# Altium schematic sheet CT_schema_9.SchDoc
size 405 x 220 mm
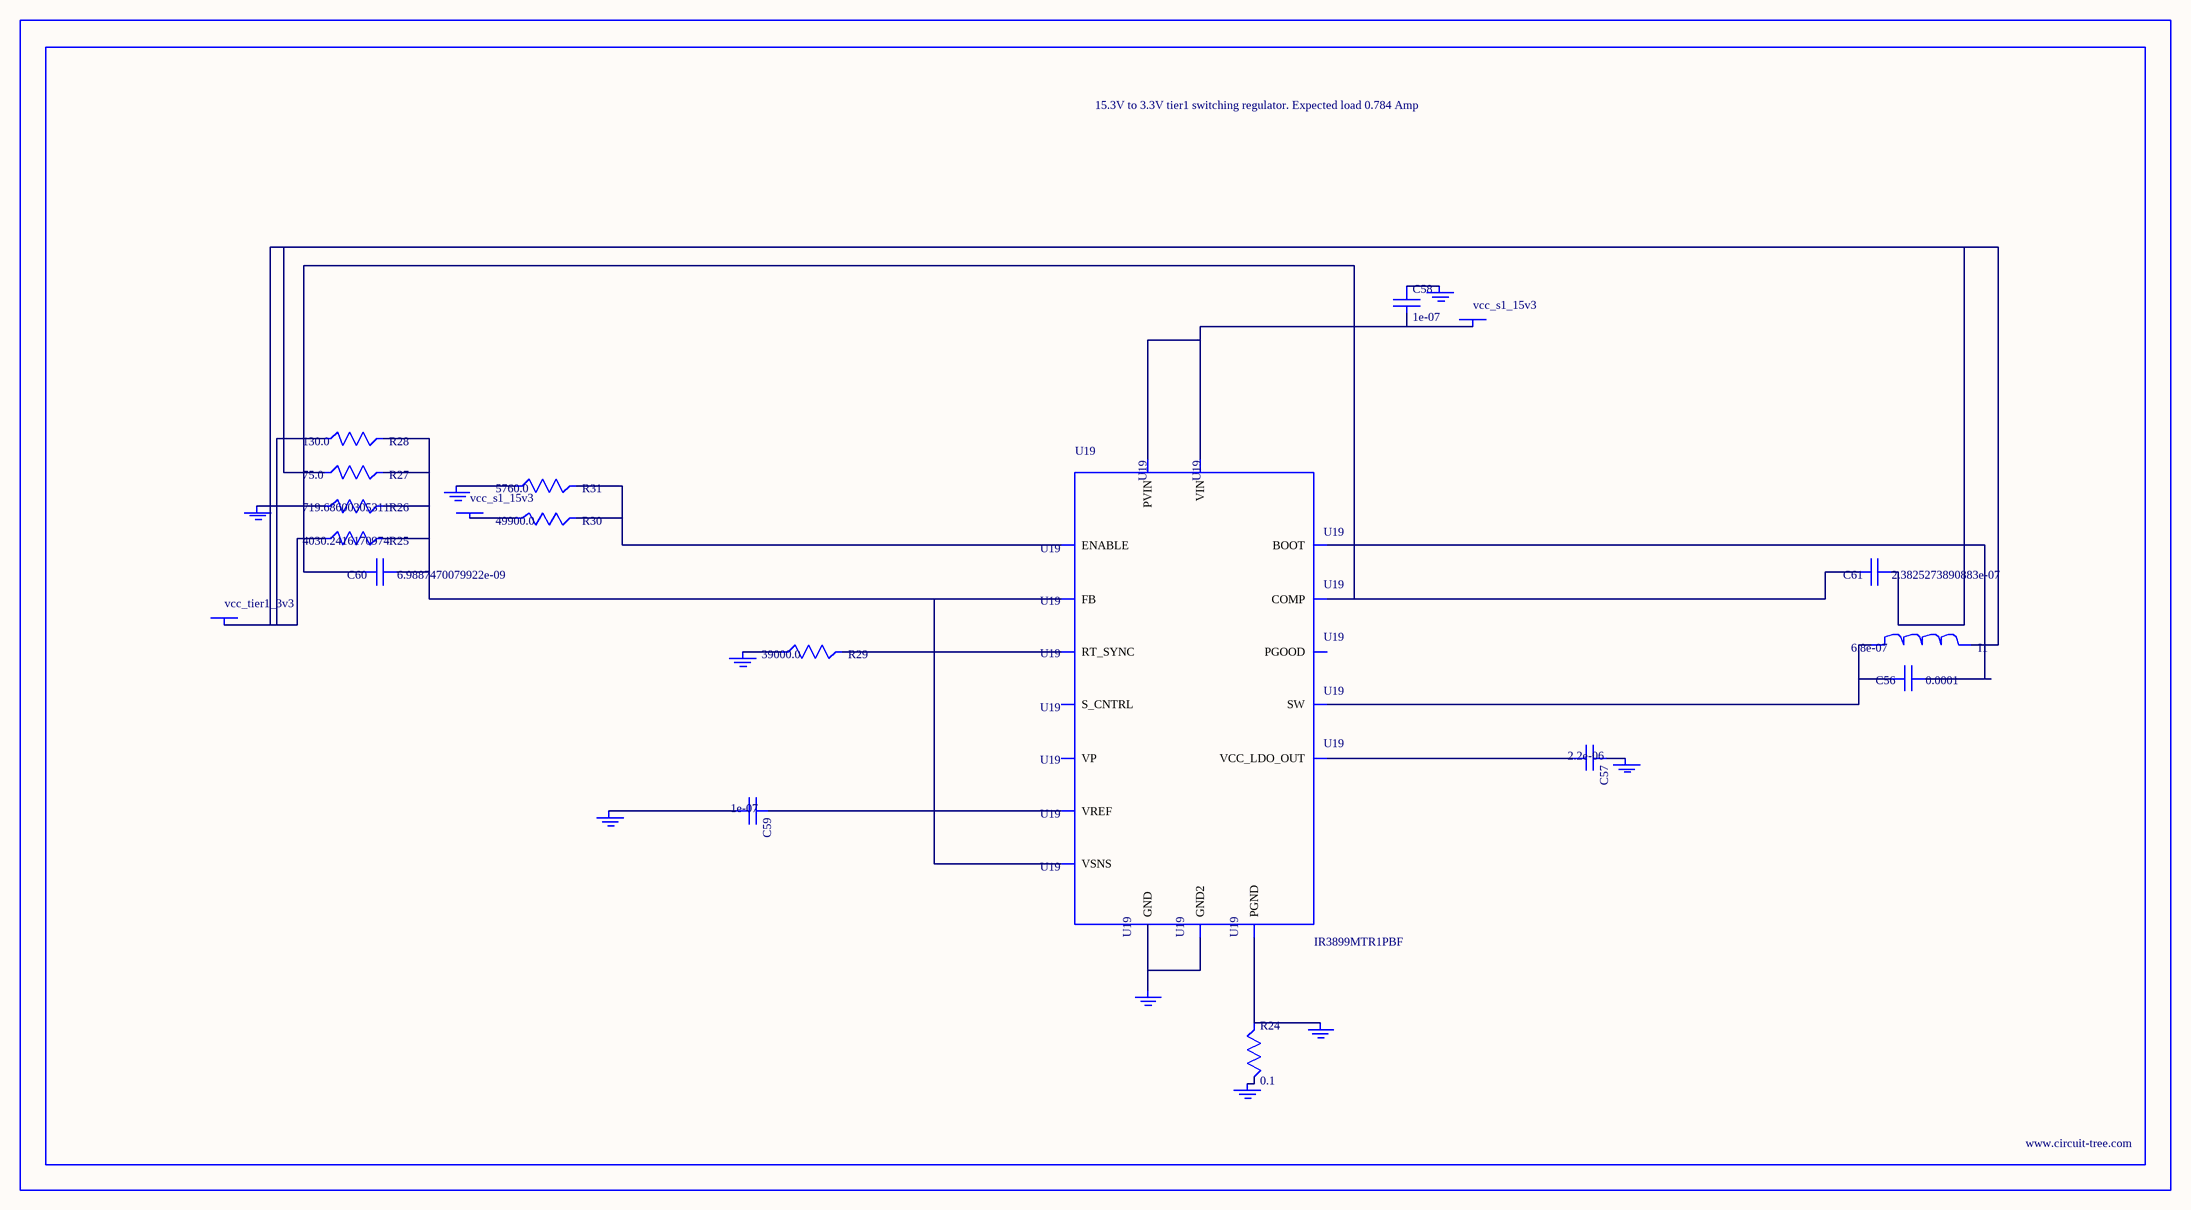
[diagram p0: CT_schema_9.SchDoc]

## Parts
BORDER8  (no value)
C56  0.0001  [C1210]
C57  2.2e-06  [C0603]
C58  1e-07  [C0402]
C59  1e-07  [C0402]
C60  6.9887470079922e-09  [R0603]
C61  2.3825273890883e-07  [R0603]
GND_INSTANCE_8_0  (no value)
GND_INSTANCE_8_1  (no value)
GND_INSTANCE_8_2  (no value)
GND_INSTANCE_8_3  (no value)
GND_INSTANCE_8_4  (no value)
GND_INSTANCE_8_5  (no value)
GND_INSTANCE_8_6  (no value)
GND_INSTANCE_8_7  (no value)
GND_INSTANCE_8_8  (no value)
I1  6.8e-07  [IND25X25CZ]
POWER_INSTANCE_8_0  vcc_s1_15v3
POWER_INSTANCE_8_1  vcc_s1_15v3
POWER_INSTANCE_8_2  vcc_tier1_3v3
R24  0.1  [R0603]
R25  4030.2416170974  [R0603]
R26  719.68600305311  [R0603]
R27  75.0  [R0603]
R28  130.0  [R0603]
R29  39000.0  [R0603]
R30  49900.0  [R0603]
R31  5760.0  [R0603]
U19  IR3899MTR1PBF  [IR3899MTR1PBF]

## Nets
NetC56_1: C56.1 U19.14(BOOT)
NetC56_2: C56.2 I1.1 U19.12(SW)
NetC57_1: C57.1 GND_INSTANCE_8_4.0(GND)
NetC57_2: C57.2 U19.10(VCC_LDO_OUT)
NetC58_1: C58.1 GND_INSTANCE_8_3.0(GND)
NetC58_2: C58.2 POWER_INSTANCE_8_0.0(PWR) U19.9(VIN) U19.13(PVIN)
NetC59_1: C59.1 U19.2(VREF)
NetC59_2: C59.2 GND_INSTANCE_8_1.0(GND)
NetC60_1: C60.1 R25.2 R26.2 R27.2 R28.2 U19.1(FB) U19.8(VSNS)
NetC60_2: C60.2 C61.2 U19.3(COMP)
NetC61_1: C61.1 I1.2 POWER_INSTANCE_8_2.0(PWR) R25.1 R27.1 R28.1
NetGND_INSTANCE_8_0_0: GND_INSTANCE_8_0.0(GND) R26.1
NetGND_INSTANCE_8_2_0: GND_INSTANCE_8_2.0(GND) R29.1
NetGND_INSTANCE_8_5_0: GND_INSTANCE_8_5.0(GND) R24.2
NetGND_INSTANCE_8_6_0: GND_INSTANCE_8_6.0(GND) R24.1 U19.11(PGND)
NetGND_INSTANCE_8_7_0: GND_INSTANCE_8_7.0(GND) R31.1
NetGND_INSTANCE_8_8_0: GND_INSTANCE_8_8.0(GND) U19.4(GND) U19.17(GND2)
NetPOWER_INSTANCE_8_1_0: POWER_INSTANCE_8_1.0(PWR) R30.1
NetR29_2: R29.2 U19.5(RT_SYNC)
NetR30_2: R30.2 R31.2 U19.15(ENABLE)

Not connected (* = marked no-connect by the designer): U19 6(S_CNTRL) 7(PGOOD) 16(VP)

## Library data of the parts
BORDER8 = BORDER_PAGE8
C56 = GRM32ER61A107ME20L
C57 = C0603C225K8RACTU
C58 C59 = C0402C104K3RACTU
C60 = C60
C61 = C61
GND_INSTANCE_8_0-GND_INSTANCE_8_8 = GND
I1 = IHLP2525CZERR68M01
POWER_INSTANCE_8_0-POWER_INSTANCE_8_2 = PWR
R24 = ERJ-3RSFR10V
R25 = R25
R26 = R26
R27 = RC0603JR-0775RL
R28 = RC0603JR-07130RL
R29 = RC0603JR-0739KL
R30 = RC0603FR-0749K9
R31 = ERJ-3EKF5760V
